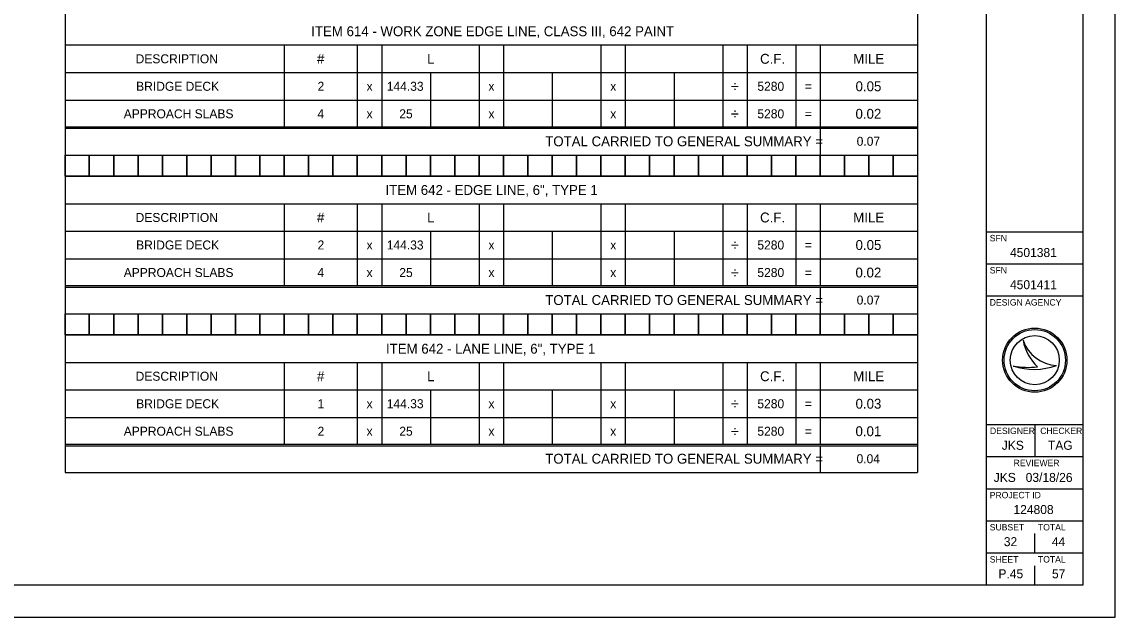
# Model space of a CAD drawing. Extents: x 0 to 34, y 0 to 22.
# Drawn here: x 17 to 34, y 0 to 9.27 of the extents above; entities that cross this region are included whole.
import ezdxf

# ---------------------------------------------------------------- set-up
doc = ezdxf.new("R2010")
doc.units = 0
for name, color, linetype in [('SH_Border', 7, 'Continuous'), ('SH_Cut_Line', 7, 'Continuous'), ('SH_Data', 7, 'Continuous'), ('SH_Text', 7, 'Continuous')]:
    doc.layers.add(name, color=color, linetype=linetype)

msp = doc.modelspace()

# ---------------------------------------------------------------- linework, layer by layer
at = {"layer": 'SH_Border'}
for p, q in [((32, 0.5), (32, 21.5)), ((32, 6), (33.5, 6)), ((32, 5.5), (33.5, 5.5)), ((32, 5), (33.5, 5)), ((32, 3), (33.5, 3)), ((32.75, 3), (32.75, 2.5)), ((32, 2.5), (33.5, 2.5)), ((32, 2), (33.5, 2)), ((32, 1.5), (33.5, 1.5)), ((32, 1), (33.5, 1))]:
    msp.add_line(p, q, dxfattribs=at)
msp.add_lwpolyline([(1.5, 21.5), (33.5, 21.5), (33.5, 0.5), (1.5, 0.5)], close=True, dxfattribs=at)
at = {"layer": 'SH_Cut_Line'}
msp.add_lwpolyline([(0, 0), (34, 0), (34, 22), (0, 22)], close=True, dxfattribs=at)
at = {"layer": 'SH_Data'}
for p, q in [((32.75, 5.675), (32.75, 5.675)), ((32.75, 5.175), (32.75, 5.175)), ((32.567, 4.31), (32.567, 4.31)), ((32.75, 4), (32.75, 4)), ((33.087, 3.919), (33.087, 3.919)), ((32.417, 3.91), (32.417, 3.91)), ((32.75, 1), (32.75, 1.3)), ((32.75, 0.5), (32.75, 0.8)), ((32.375, 0.675), (32.375, 0.675))]:
    msp.add_line(p, q, dxfattribs=at)
for radius in [0.5, 0.477, 0.477, 0.382]:
    msp.add_circle((32.75, 4), radius, dxfattribs=at)
for centre, radius, start, end in [((33.116, 4.498), 0.58, 198.9257, 198.9319), ((33.347, 4.47), 0.796, 191.6379, 191.6421), ((33.116, 4.498), 0.58, 198.9319, 267.1657), ((33.347, 4.47), 0.796, 191.6421, 226.0947), ((32.739, 4.87), 1.013, 251.4576, 290.0832), ((32.648, 5.154), 1.266, 259.4964, 259.4995), ((32.739, 4.87), 1.013, 251.4527, 251.4576), ((32.648, 5.154), 1.266, 259.4995, 276.6672)]:
    msp.add_arc(centre, radius, start, end, dxfattribs=at)
at = {"layer": 'SH_Text'}
for p, q in [((17.671, 10.102), (17.671, 7.61)), ((30.929, 10.102), (30.929, 7.61)), ((17.671, 8.906), (30.929, 8.906)), ((21.08, 8.906), (21.08, 7.632)), ((22.216, 8.906), (22.216, 7.632)), ((22.595, 8.906), (22.595, 7.632)), ((24.111, 8.906), (24.111, 7.632)), ((24.489, 8.906), (24.489, 7.632)), ((26.005, 8.906), (26.005, 7.632)), ((26.383, 8.906), (26.383, 7.632)), ((27.899, 8.906), (27.899, 7.632)), ((28.278, 8.906), (28.278, 7.632)), ((29.035, 8.906), (29.035, 7.632)), ((29.414, 8.906), (29.414, 7.632)), ((17.671, 8.477), (30.929, 8.477)), ((23.353, 8.477), (23.353, 7.632)), ((25.247, 8.477), (25.247, 7.632)), ((27.141, 8.477), (27.141, 7.632)), ((17.671, 8.049), (30.929, 8.049)), ((17.671, 7.632), (30.929, 7.632)), ((17.671, 7.632), (17.671, 5.139)), ((17.671, 7.61), (30.929, 7.61)), ((29.414, 7.61), (29.414, 7.193)), ((30.929, 7.632), (30.929, 5.139)), ((17.671, 7.193), (30.929, 7.193)), ((17.671, 6.863), (30.929, 6.863)), ((17.671, 6.435), (30.929, 6.435)), ((21.08, 6.435), (21.08, 5.161)), ((22.216, 6.435), (22.216, 5.161)), ((22.595, 6.435), (22.595, 5.161)), ((24.111, 6.435), (24.111, 5.161)), ((24.489, 6.435), (24.489, 5.161)), ((26.005, 6.435), (26.005, 5.161)), ((26.383, 6.435), (26.383, 5.161)), ((27.899, 6.435), (27.899, 5.161)), ((28.278, 6.435), (28.278, 5.161)), ((29.035, 6.435), (29.035, 5.161)), ((29.414, 6.435), (29.414, 5.161)), ((17.671, 6.007), (30.929, 6.007)), ((23.353, 6.007), (23.353, 5.161)), ((25.247, 6.007), (25.247, 5.161)), ((27.141, 6.007), (27.141, 5.161)), ((17.671, 5.578), (30.929, 5.578)), ((17.671, 5.161), (30.929, 5.161)), ((17.671, 5.161), (17.671, 2.669)), ((17.671, 5.139), (30.929, 5.139)), ((29.414, 5.139), (29.414, 4.722)), ((30.929, 5.161), (30.929, 2.669)), ((17.671, 4.722), (30.929, 4.722)), ((17.671, 4.393), (30.929, 4.393)), ((17.671, 3.964), (30.929, 3.964)), ((21.08, 3.964), (21.08, 2.691)), ((22.216, 3.964), (22.216, 2.691)), ((22.595, 3.964), (22.595, 2.691)), ((24.111, 3.964), (24.111, 2.691)), ((24.489, 3.964), (24.489, 2.691)), ((26.005, 3.964), (26.005, 2.691)), ((26.383, 3.964), (26.383, 2.691)), ((27.899, 3.964), (27.899, 2.691)), ((28.278, 3.964), (28.278, 2.691)), ((29.035, 3.964), (29.035, 2.691)), ((29.414, 3.964), (29.414, 2.691)), ((17.671, 3.536), (30.929, 3.536)), ((23.353, 3.536), (23.353, 2.691)), ((25.247, 3.536), (25.247, 2.691)), ((27.141, 3.536), (27.141, 2.691)), ((17.671, 3.108), (30.929, 3.108)), ((17.671, 2.691), (30.929, 2.691)), ((17.671, 2.691), (17.671, 2.251)), ((17.671, 2.669), (30.929, 2.669)), ((29.414, 2.669), (29.414, 2.251)), ((30.929, 2.691), (30.929, 2.251)), ((17.671, 2.251), (30.929, 2.251))]:
    msp.add_line(p, q, dxfattribs=at)
for points in [[(17.671, 7.193), (18.049, 7.193), (18.049, 6.863), (17.671, 6.863)], [(18.049, 7.193), (18.428, 7.193), (18.428, 6.863), (18.049, 6.863)], [(18.428, 7.193), (18.807, 7.193), (18.807, 6.863), (18.428, 6.863)], [(18.807, 7.193), (19.186, 7.193), (19.186, 6.863), (18.807, 6.863)], [(19.186, 7.193), (19.565, 7.193), (19.565, 6.863), (19.186, 6.863)], [(19.565, 7.193), (19.943, 7.193), (19.943, 6.863), (19.565, 6.863)], [(19.943, 7.193), (20.322, 7.193), (20.322, 6.863), (19.943, 6.863)], [(20.322, 7.193), (20.701, 7.193), (20.701, 6.863), (20.322, 6.863)], [(20.701, 7.193), (21.08, 7.193), (21.08, 6.863), (20.701, 6.863)], [(21.08, 7.193), (21.459, 7.193), (21.459, 6.863), (21.08, 6.863)], [(21.459, 7.193), (21.838, 7.193), (21.838, 6.863), (21.459, 6.863)], [(21.838, 7.193), (22.216, 7.193), (22.216, 6.863), (21.838, 6.863)], [(22.216, 7.193), (22.595, 7.193), (22.595, 6.863), (22.216, 6.863)], [(22.595, 7.193), (22.974, 7.193), (22.974, 6.863), (22.595, 6.863)], [(22.974, 7.193), (23.353, 7.193), (23.353, 6.863), (22.974, 6.863)], [(23.353, 7.193), (23.732, 7.193), (23.732, 6.863), (23.353, 6.863)], [(23.732, 7.193), (24.111, 7.193), (24.111, 6.863), (23.732, 6.863)], [(24.111, 7.193), (24.489, 7.193), (24.489, 6.863), (24.111, 6.863)], [(24.489, 7.193), (24.868, 7.193), (24.868, 6.863), (24.489, 6.863)], [(24.868, 7.193), (25.247, 7.193), (25.247, 6.863), (24.868, 6.863)], [(25.247, 7.193), (25.626, 7.193), (25.626, 6.863), (25.247, 6.863)], [(25.626, 7.193), (26.005, 7.193), (26.005, 6.863), (25.626, 6.863)], [(26.005, 7.193), (26.383, 7.193), (26.383, 6.863), (26.005, 6.863)], [(26.383, 7.193), (26.762, 7.193), (26.762, 6.863), (26.383, 6.863)], [(26.762, 7.193), (27.141, 7.193), (27.141, 6.863), (26.762, 6.863)], [(27.141, 7.193), (27.52, 7.193), (27.52, 6.863), (27.141, 6.863)], [(27.52, 7.193), (27.899, 7.193), (27.899, 6.863), (27.52, 6.863)], [(27.899, 7.193), (28.278, 7.193), (28.278, 6.863), (27.899, 6.863)], [(28.278, 7.193), (28.656, 7.193), (28.656, 6.863), (28.278, 6.863)], [(28.656, 7.193), (29.035, 7.193), (29.035, 6.863), (28.656, 6.863)], [(29.035, 7.193), (29.414, 7.193), (29.414, 6.863), (29.035, 6.863)], [(29.414, 7.193), (29.793, 7.193), (29.793, 6.863), (29.414, 6.863)], [(29.793, 7.193), (30.172, 7.193), (30.172, 6.863), (29.793, 6.863)], [(30.172, 7.193), (30.551, 7.193), (30.551, 6.863), (30.172, 6.863)], [(30.551, 7.193), (30.929, 7.193), (30.929, 6.863), (30.551, 6.863)], [(17.671, 4.722), (18.049, 4.722), (18.049, 4.393), (17.671, 4.393)], [(18.049, 4.722), (18.428, 4.722), (18.428, 4.393), (18.049, 4.393)], [(18.428, 4.722), (18.807, 4.722), (18.807, 4.393), (18.428, 4.393)], [(18.807, 4.722), (19.186, 4.722), (19.186, 4.393), (18.807, 4.393)], [(19.186, 4.722), (19.565, 4.722), (19.565, 4.393), (19.186, 4.393)], [(19.565, 4.722), (19.943, 4.722), (19.943, 4.393), (19.565, 4.393)], [(19.943, 4.722), (20.322, 4.722), (20.322, 4.393), (19.943, 4.393)], [(20.322, 4.722), (20.701, 4.722), (20.701, 4.393), (20.322, 4.393)], [(20.701, 4.722), (21.08, 4.722), (21.08, 4.393), (20.701, 4.393)], [(21.08, 4.722), (21.459, 4.722), (21.459, 4.393), (21.08, 4.393)], [(21.459, 4.722), (21.838, 4.722), (21.838, 4.393), (21.459, 4.393)], [(21.838, 4.722), (22.216, 4.722), (22.216, 4.393), (21.838, 4.393)], [(22.216, 4.722), (22.595, 4.722), (22.595, 4.393), (22.216, 4.393)], [(22.595, 4.722), (22.974, 4.722), (22.974, 4.393), (22.595, 4.393)], [(22.974, 4.722), (23.353, 4.722), (23.353, 4.393), (22.974, 4.393)], [(23.353, 4.722), (23.732, 4.722), (23.732, 4.393), (23.353, 4.393)], [(23.732, 4.722), (24.111, 4.722), (24.111, 4.393), (23.732, 4.393)], [(24.111, 4.722), (24.489, 4.722), (24.489, 4.393), (24.111, 4.393)], [(24.489, 4.722), (24.868, 4.722), (24.868, 4.393), (24.489, 4.393)], [(24.868, 4.722), (25.247, 4.722), (25.247, 4.393), (24.868, 4.393)], [(25.247, 4.722), (25.626, 4.722), (25.626, 4.393), (25.247, 4.393)], [(25.626, 4.722), (26.005, 4.722), (26.005, 4.393), (25.626, 4.393)], [(26.005, 4.722), (26.383, 4.722), (26.383, 4.393), (26.005, 4.393)], [(26.383, 4.722), (26.762, 4.722), (26.762, 4.393), (26.383, 4.393)], [(26.762, 4.722), (27.141, 4.722), (27.141, 4.393), (26.762, 4.393)], [(27.141, 4.722), (27.52, 4.722), (27.52, 4.393), (27.141, 4.393)], [(27.52, 4.722), (27.899, 4.722), (27.899, 4.393), (27.52, 4.393)], [(27.899, 4.722), (28.278, 4.722), (28.278, 4.393), (27.899, 4.393)], [(28.278, 4.722), (28.656, 4.722), (28.656, 4.393), (28.278, 4.393)], [(28.656, 4.722), (29.035, 4.722), (29.035, 4.393), (28.656, 4.393)], [(29.035, 4.722), (29.414, 4.722), (29.414, 4.393), (29.035, 4.393)], [(29.414, 4.722), (29.793, 4.722), (29.793, 4.393), (29.414, 4.393)], [(29.793, 4.722), (30.172, 4.722), (30.172, 4.393), (29.793, 4.393)], [(30.172, 4.722), (30.551, 4.722), (30.551, 4.393), (30.172, 4.393)], [(30.551, 4.722), (30.929, 4.722), (30.929, 4.393), (30.551, 4.393)]]:
    msp.add_lwpolyline(points, close=True, dxfattribs=at)

# ---------------------------------------------------------------- texts
at = {"layer": 'SH_Data'}
for s, height, p in [('SFN', 0.1, (32.05, 5.85)), ('4501381', 0.14, (32.365, 5.605)), ('SFN', 0.1, (32.05, 5.35)), ('4501411', 0.14, (32.365, 5.105)), ('DESIGN AGENCY', 0.1, (32.05, 4.85)), ('DESIGNER', 0.1, (32.054, 2.85)), ('CHECKER', 0.1, (32.835, 2.85)), ('JKS', 0.14, (32.237, 2.605)), ('TAG', 0.14, (32.955, 2.605)), ('REVIEWER', 0.1, (32.422, 2.35)), ('JKS', 0.14, (32.112, 2.105)), ('03/18/26', 0.14, (32.609, 2.105)), ('PROJECT ID', 0.1, (32.05, 1.85)), ('124808', 0.14, (32.419, 1.605)), ('SUBSET', 0.1, (32.05, 1.35)), ('TOTAL', 0.1, (32.8, 1.35)), ('32', 0.14, (32.269, 1.105)), ('44', 0.14, (33.016, 1.105)), ('SHEET', 0.1, (32.05, 0.85)), ('TOTAL', 0.1, (32.8, 0.85)), ('P.45', 0.14, (32.185, 0.605)), ('57', 0.14, (33.018, 0.605))]:
    msp.add_text(s, height=height, dxfattribs=at).set_placement(p)
at = {"layer": 'SH_Text'}
for s, height, p in [('ITEM 614 - WORK ZONE EDGE LINE, CLASS III, 642 PAINT', 0.154, (21.5, 9.043)), ('DESCRIPTION', 0.14, (18.769, 8.621)), ('#', 0.154, (21.589, 8.614)), ('L', 0.154, (23.302, 8.614)), ('C.F.', 0.154, (28.479, 8.614)), ('MILE', 0.154, (29.928, 8.614)), ('BRIDGE DECK', 0.14, (18.777, 8.193)), ('2', 0.14, (21.598, 8.193)), ('144.33', 0.14, (22.674, 8.193)), ('5280', 0.14, (28.437, 8.193)), ('0.05', 0.154, (29.964, 8.186)), ('x', 0.14, (22.36, 8.193)), ('x', 0.14, (24.255, 8.193)), ('x', 0.14, (26.149, 8.193)), ('÷', 0.168, (28.026, 8.179)), ('=', 0.14, (29.175, 8.193)), ('APPROACH SLABS', 0.14, (18.584, 7.765)), ('4', 0.14, (21.595, 7.765)), ('x', 0.14, (22.36, 7.765)), ('25', 0.14, (22.869, 7.765)), ('x', 0.14, (24.255, 7.765)), ('x', 0.14, (26.149, 7.765)), ('÷', 0.168, (28.026, 7.751)), ('5280', 0.14, (28.437, 7.765)), ('=', 0.14, (29.175, 7.765)), ('0.02', 0.154, (29.963, 7.758)), ('TOTAL CARRIED TO GENERAL SUMMARY =', 0.154, (25.138, 7.33)), ('0.07', 0.14, (29.981, 7.337)), ('ITEM 642 - EDGE LINE, 6", TYPE 1', 0.154, (22.654, 6.572)), ('DESCRIPTION', 0.14, (18.769, 6.151)), ('#', 0.154, (21.589, 6.144)), ('L', 0.154, (23.302, 6.144)), ('C.F.', 0.154, (28.479, 6.144)), ('MILE', 0.154, (29.928, 6.144)), ('BRIDGE DECK', 0.14, (18.777, 5.723)), ('2', 0.14, (21.598, 5.723)), ('x', 0.14, (22.36, 5.723)), ('144.33', 0.14, (22.674, 5.723)), ('x', 0.14, (24.255, 5.723)), ('x', 0.14, (26.149, 5.723)), ('÷', 0.168, (28.026, 5.709)), ('5280', 0.14, (28.437, 5.723)), ('=', 0.14, (29.175, 5.723)), ('0.05', 0.154, (29.964, 5.716)), ('0.02', 0.154, (29.963, 5.287)), ('APPROACH SLABS', 0.14, (18.584, 5.294)), ('4', 0.14, (21.595, 5.294)), ('x', 0.14, (22.36, 5.294)), ('25', 0.14, (22.869, 5.294)), ('x', 0.14, (24.255, 5.294)), ('x', 0.14, (26.149, 5.294)), ('÷', 0.168, (28.026, 5.28)), ('5280', 0.14, (28.437, 5.294)), ('=', 0.14, (29.175, 5.294)), ('TOTAL CARRIED TO GENERAL SUMMARY =', 0.154, (25.138, 4.859)), ('0.07', 0.14, (29.981, 4.866)), ('ITEM 642 - LANE LINE, 6", TYPE 1', 0.154, (22.662, 4.101)), ('DESCRIPTION', 0.14, (18.769, 3.68)), ('#', 0.154, (21.589, 3.673)), ('L', 0.154, (23.302, 3.673)), ('C.F.', 0.154, (28.479, 3.673)), ('MILE', 0.154, (29.928, 3.673)), ('0.03', 0.154, (29.964, 3.245)), ('BRIDGE DECK', 0.14, (18.777, 3.252)), ('1', 0.14, (21.598, 3.252)), ('x', 0.14, (22.36, 3.252)), ('144.33', 0.14, (22.674, 3.252)), ('x', 0.14, (24.255, 3.252)), ('x', 0.14, (26.149, 3.252)), ('÷', 0.168, (28.026, 3.238)), ('5280', 0.14, (28.437, 3.252)), ('=', 0.14, (29.175, 3.252)), ('APPROACH SLABS', 0.14, (18.584, 2.824)), ('2', 0.14, (21.598, 2.824)), ('x', 0.14, (22.36, 2.824)), ('25', 0.14, (22.869, 2.824)), ('x', 0.14, (24.255, 2.824)), ('x', 0.14, (26.149, 2.824)), ('÷', 0.168, (28.026, 2.81)), ('5280', 0.14, (28.437, 2.824)), ('=', 0.14, (29.175, 2.824)), ('0.01', 0.154, (29.963, 2.817)), ('TOTAL CARRIED TO GENERAL SUMMARY =', 0.154, (25.138, 2.389)), ('0.04', 0.14, (29.979, 2.396))]:
    msp.add_text(s, height=height, dxfattribs=at).set_placement(p)

doc.saveas('drawing.dxf')
